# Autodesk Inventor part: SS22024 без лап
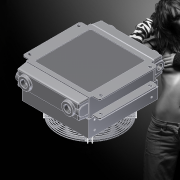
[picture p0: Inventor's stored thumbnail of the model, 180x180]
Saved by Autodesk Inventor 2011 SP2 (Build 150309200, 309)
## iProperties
Created: 2015-12
Part Number: SS22024 без лап
Material: Сталь
Document SubType Name: Modeling
Designer: Дорохин
Mass: 7000 g
Surface Area: 5612.32 cm^2
Volume: 4411.6 cm^3
Density: 1.58673 g/cm^3
Author: Дорохин
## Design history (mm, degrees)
derived "374_SS2200300A-PE.iam"
sketch "Эскиз2"
  geometry: L1 (230, 0)-(0, 0) reference; L2 (-25, -216.5)-(-25, -16.5) reference; L3 (0, -233)-(230, -233) reference; L4 (255, -16.5)-(255, -216.5) reference; L5 (20, -218)-(210, -218); L6 (215, -213)-(215, -20); L7 (210, -15)-(20, -15); L8 (15, -20)-(15, -213); A1 r 5 centre (20, -213) between (15, -213) and (20, -218); A2 r 5 centre (20, -20) between (20, -15) and (15, -20); A3 r 5 centre (210, -20) between (215, -20) and (210, -15); A4 r 5 centre (210, -213) between (210, -218) and (215, -213); 1 further point
  constraints: 8 end point, 8 point on circle, 8 tangent, 4 centre point, 3 equal radius, 2 parallel, 1 horizontal, 1 perpendicular
  dimensions: "d1" = 40 distance between parallel lines of L4 L6; "d2" = 40 distance between parallel lines of L2 L8 (= d1); "d3" = 15 distance between parallel lines of L3 L5; "d4" = 15 distance between parallel lines of L1 L7 (= d3); "d5" = 5 radius of A1
extrude "Выдавливание1" cut sketch "Эскиз2" distance "d6" = 2; taper "d7" = 0 deg
feature "Резьба1" dims "d8" = 10, "d9" = 0
feature "Резьба2" dims "d10" = 10, "d11" = 0
feature "Резьба3" dims "d12" = 10, "d13" = 0
sketch "Эскиз3"
  geometry: L1 (-155, 0)-(0, 0) reference; L2 (0, 29.5)-(0, 0) reference; L3 (-155, 0)-(0, 0); L4 (0, 0)-(0, 47.5); L5 (0, 47.5)-(-155, 47.5); L6 (-155, 47.5)-(-155, 0); L7 (-155, 305)-(0, 305); L8 (0, 305)-(0, 257.5); L9 (0, 257.5)-(-155, 257.5); L10 (-155, 257.5)-(-155, 305); L11 (0.5, 302)-(0.5, 275.5) reference; L12 (-92.5, 47.5)-(-96.5, 47.5) reference; L13 (-40, 59.5)-(-40, 37) reference; L14 (-40, 47.5)-(-91.5, 47.5); L15 (-91.5, 47.5)-(-91.5, 59.5); L16 (-91.5, 59.5)-(-40, 59.5); L17 (-40, 59.5)-(-40, 47.5); L18 (-39.5, 268)-(-39.5, 248.5) reference; L19 (-91.5, 59.5)-(-91.5, 247.5) reference; L20 (-39.5, 257.5)-(-91.5, 257.5); L21 (-91.5, 257.5)-(-91.5, 245.5); L22 (-91.5, 245.5)-(-39.5, 245.5); L23 (-39.5, 245.5)-(-39.5, 257.5); L24 (0, 257.5)-(21, 257.5); L25 (21, 257.5)-(21, 305); L26 (21, 305)-(0, 305); L27 (0, 305)-(0, 257.5); C1 r 8.25 at (-140, 15) reference; C2 r 8.25 at (-15, 15) reference; 1 further point
  constraints: 40 end point, 11 parallel, 6 point on line, 5 horizontal, 5 perpendicular, 1 collinear
  dimensions: "d14" = 0 distance between parallel lines of L10 L6; "d15" = 0 distance between parallel lines of L8 L4; "d16" = 305 distance between parallel lines of L7 L1; "d17" = 47.5 distance between parallel lines of L1 L5; "d18" = 47.5 distance between parallel lines of L7 L9 (= d17); "d20" = 12 distance between parallel lines of L20 L22
extrude "Выдавливание2" cut sketch "Эскиз3" distance "d21" = 42; taper "d22" = 0 deg
sketch "Эскиз4"
  geometry: L1 (0, 110)-(70, 110) reference; L2 (70, 110)-(70, 0) reference; L3 (70, 0)-(0, 0) reference; L4 (0, 0)-(0, 110) reference; L5 (-5, 115)-(75, 115); L6 (75, 115)-(75, -5); L7 (75, -5)-(-5, -5); L8 (-5, -5)-(-5, 115); 1 further point
  constraints: 8 end point, 2 parallel, 1 horizontal, 1 perpendicular
extrude "Выдавливание3" cut sketch "Эскиз4" distance "d23" = 50; taper "d24" = 0 deg
node "Твердое тело1"
node "None.ipt:1"
node "None_1.ipt:1"
feature "Производный составной элемент1"
node "Проецирование ребер1"
